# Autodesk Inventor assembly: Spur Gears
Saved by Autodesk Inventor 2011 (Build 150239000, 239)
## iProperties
Created: 2010-04
Part Number: Spur Gears
Document SubType Name: Assembly
Designer: Phil
Categories: <?xml version="1.0" encoding="UTF-16"?> <MemberInstance><Categories><FamilyTemplate/><ParamToTemplateMap><ParamToTemplate><ParamToTemplate CategoryParameter="//
ClientObjectVersion: 1
Author: Phil
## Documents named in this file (3)
- C:\Data Folder\VEX 2011\Inventor Datasets\Unit 6\DesignGears\Design Accelerator\Spur Gears1.iam
- C:\Data Folder\VEX 2011\Inventor Datasets\Unit 6\DesignGears\Design Accelerator\Spur Gear11.ipt
- C:\Data Folder\VEX 2011\Inventor Datasets\Unit 6\DesignGears\Design Accelerator\Spur Gear21.ipt
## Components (2 placed, 2 different names)
1. Spur Gear1:1 — Rotation:1
2. Spur Gear2:1 — Rotation:1
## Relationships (1: RelateRotation 1)
- Rotation:1 [RelateRotation]: Spur Gear1:1 ↔ Spur Gear2:1
